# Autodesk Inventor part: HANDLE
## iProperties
Author: GJOHNST2
Shininess: 20.0
Length Units: 11272
Angle Units: 11286
Time Units: 11279
Mass Units: 11290
Length Display Precision: 3
Angle Display Precision: 2
Compacted: True
PropertySet Name: _Private Model Information
Created: 2001-11
Part Number: HANDLE
Material: Stainless Steel, Austenitic
Document SubType Name: Sheet Metal
Designer: GJOHNST2
Control State: 0
Master: False
Checked Out: False
PropertySet Name: Design Tracking Control
Density: 8.03
Volumn: 33.56231636477584
Area: 142.61751534446216
PropertySet Name: Model Information
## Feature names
1. Corner Round1
2. Corner Round2
3. Plate1
4. Plate2
5. Bend1
6. Plate3
7. Bend2
8. Plate4
9. Bend3
